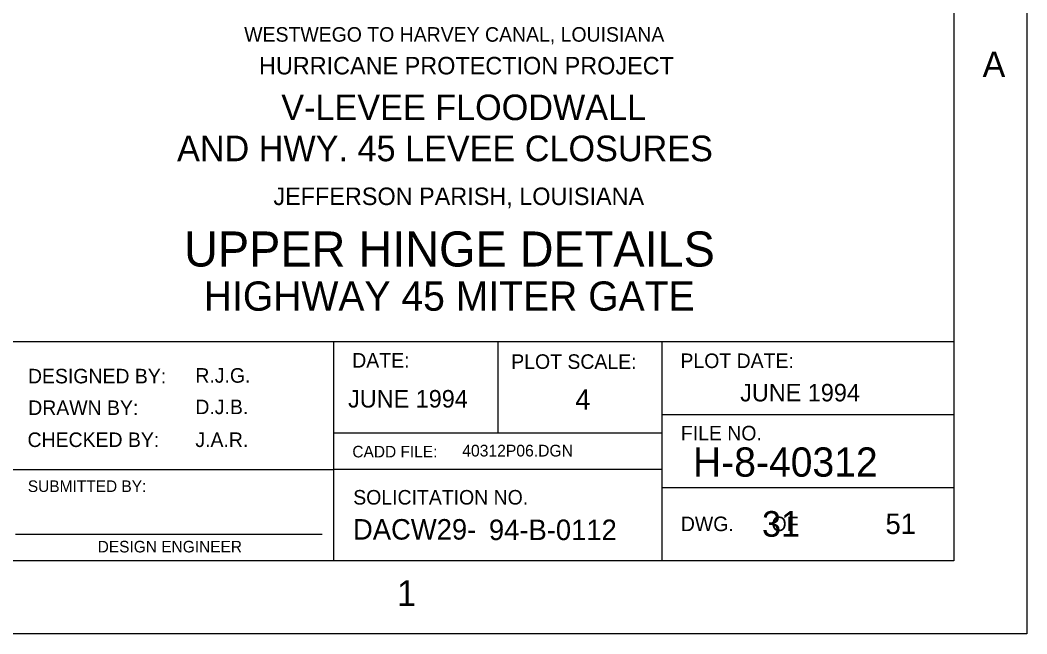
# Model space of a CAD drawing. Extents: x 0.1 to 13.5, y 0.1 to 9.5.
# Drawn here: x 11.157 to 13.457, y 0.124 to 1.525 of the extents above; entities that cross this region are included whole.
import ezdxf

# ---------------------------------------------------------------- set-up
doc = ezdxf.new("R2010")
doc.units = 0
doc.layers.add('Level 1', color=7, linetype='Continuous')
doc.layers.add('Level 2', color=7, linetype='Continuous')

msp = doc.modelspace()

# ---------------------------------------------------------------- linework, layer by layer
at = {"layer": 'Level 1'}
for p, q in [((13.2904, 0.7903), (11.1238, 0.7903)), ((11.8738, 0.2903), (11.8738, 0.7903)), ((12.2488, 0.5819), (12.2488, 0.7903)), ((12.6238, 0.2903), (12.6238, 0.7903)), ((13.2904, 0.6236), (12.6238, 0.6236)), ((12.6238, 0.5819), (11.8738, 0.5819)), ((11.1238, 0.4986), (11.8738, 0.4986)), ((12.6238, 0.4986), (11.8738, 0.4986)), ((13.2904, 0.4569), (12.6238, 0.4569)), ((11.1462, 0.3514), (11.8472, 0.3514))]:
    msp.add_line(p, q, dxfattribs=at)
for points in [[(0.1238, 9.4569), (13.4571, 9.4569), (13.4571, 0.1236), (0.1238, 0.1236)], [(0.6238, 9.2903), (13.2904, 9.2903), (13.2904, 0.2903), (0.6238, 0.2903)]]:
    msp.add_lwpolyline(points, close=True, dxfattribs=at)

# ---------------------------------------------------------------- texts
for s, height, p in [('A', 0.0584, (13.3558, 1.3947)), ('DATE:', 0.03321, (11.9157, 0.7315)), ('PLOT SCALE:', 0.033208, (12.279, 0.7286)), ('PLOT DATE:', 0.03321, (12.6656, 0.7305)), ('DESIGNED BY:', 0.033208, (11.1748, 0.6955)), ('DRAWN BY:', 0.03321, (11.1754, 0.6233)), ('FILE NO.', 0.03321, (12.6665, 0.5653)), ('CHECKED BY:', 0.033208, (11.1738, 0.5502)), ('CADD FILE:', 0.02642, (11.916, 0.5264)), ('SUBMITTED BY:', 0.026417, (11.1745, 0.4475)), ('SOLICITATION NO.', 0.033208, (11.918, 0.4188)), ('DWG.       OF', 0.033208, (12.6665, 0.3581)), ('DACW29-', 0.04679, (11.9175, 0.3388)), ('DESIGN ENGINEER', 0.026417, (11.3341, 0.3095)), ('1', 0.0584, (12.0179, 0.1873))]:
    msp.add_text(s, height=height, dxfattribs=at).set_placement(p)
at = {"layer": 'Level 2'}
for s, height, p in [('WESTWEGO TO HARVEY CANAL, LOUISIANA', 0.033208, (11.6689, 1.4756)), ('HURRICANE PROTECTION PROJECT', 0.04, (11.7027, 1.4009)), ('V-LEVEE FLOODWALL', 0.058417, (11.7536, 1.2965)), ('AND HWY. 45 LEVEE CLOSURES', 0.058417, (11.5155, 1.2027)), ('JEFFERSON PARISH, LOUISIANA', 0.04, (11.7356, 1.1026)), (' UPPER HINGE DETAILS', 0.08, (11.5018, 0.9623)), ('HIGHWAY 45 MITER GATE', 0.066792, (11.5765, 0.8614)), ('R.J.G.', 0.03321, (11.5573, 0.697)), ('JUNE 1994', 0.04, (12.8021, 0.6543)), ('JUNE 1994', 0.04, (11.9062, 0.6403)), ('4', 0.0468, (12.4254, 0.6354)), ('D.J.B.', 0.03321, (11.5573, 0.6252)), ('J.A.R.', 0.03321, (11.5573, 0.5502)), ('40312P06.DGN', 0.026792, (12.1671, 0.5285)), ('H-8-40312', 0.06679, (12.6942, 0.4825)), ('31', 0.05842, (12.852, 0.3454)), ('51', 0.04679, (13.1341, 0.3515)), ('94-B-0112', 0.04679, (12.228, 0.3377))]:
    msp.add_text(s, height=height, dxfattribs=at).set_placement(p)

doc.saveas('drawing.dxf')
